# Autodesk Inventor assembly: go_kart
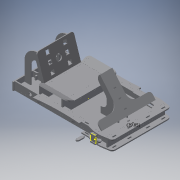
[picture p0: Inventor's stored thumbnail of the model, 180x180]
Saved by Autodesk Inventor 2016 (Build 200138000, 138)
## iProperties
Created: 2017-06
Part Number: go_kart
Document SubType Name: Assembly
Designer: laboratorioesan
Author: laboratorioesan
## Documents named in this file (25)
- C:\Users\laboratorioesan\Desktop\Proyecto final\go_kart.iam
- C:\Users\laboratorioesan\Desktop\Proyecto final\marco_lateral.ipt
- C:\Users\laboratorioesan\Desktop\Proyecto final\Part3.ipt
- C:\Users\laboratorioesan\Desktop\Proyecto final\marco_frontal.ipt
- C:\Users\laboratorioesan\Desktop\Proyecto final\base_marco.ipt
- C:\Users\laboratorioesan\Desktop\Proyecto final\transversal_marco.ipt
- C:\Users\laboratorioesan\Desktop\Proyecto final\asiento_base.ipt
- C:\Users\laboratorioesan\Desktop\Proyecto final\asiento_lateral.ipt
- C:\Users\laboratorioesan\Desktop\Proyecto final\fenders.ipt
- C:\Users\laboratorioesan\Desktop\Proyecto final\nervio_fender.ipt
- C:\Users\laboratorioesan\Desktop\Proyecto final\marco_frontal_1.ipt
- C:\Users\laboratorioesan\Desktop\Proyecto final\mascara_frontal.ipt
- C:\Users\laboratorioesan\Desktop\Proyecto final\uniones_mascara.ipt
- C:\Users\laboratorioesan\Desktop\Proyecto final\acople_nuevo.ipt
- C:\Users\laboratorioesan\Desktop\Proyecto final\acople_union_1.ipt
- C:\Users\laboratorioesan\Desktop\Proyecto final\acople_eje.ipt
- C:\Users\laboratorioesan\Desktop\Proyecto final\frontal_timon_estructura.ipt
- C:\Users\laboratorioesan\Desktop\Proyecto final\lateral_timon_estructura.ipt
- C:\Users\laboratorioesan\Desktop\Proyecto final\union_mascara.ipt
- C:\Users\laboratorioesan\Desktop\Proyecto final\espaldar_asiento.ipt
- C:\Users\laboratorioesan\Desktop\Proyecto final\espaldar_union_vertical.ipt
- C:\Users\laboratorioesan\Desktop\Proyecto final\chumaceras.ipt
- C:\Users\laboratorioesan\Desktop\Proyecto final\Soporte_eje_pequeño.ipt
- C:\Users\laboratorioesan\Desktop\Proyecto final\acople_union_2.ipt
- C:\Users\laboratorioesan\Desktop\Proyecto final\union_eje_pequeño.ipt
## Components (36 placed, 24 different names)
1. marco_lateral:1 — Flush:1, Mate:4, Mate:6, Mate:7, Flush:2, Flush:3, Mate:14, Mate:15, Mate:22, Mate:23, Mate:24, Mate:25, Mate:26, Mate:27, Mate:28
2. Part3:1 — Flush:1, Mate:1, Mate:2, Mate:3
3. marco_lateral:4 — Mate:1, Mate:2, Mate:3, Mate:5, Mate:8, Mate:9, Mate:13, Flush:6, Flush:7, Mate:19
4. marco_frontal:1 — Mate:4, Mate:5, Mate:6, Mate:7, Mate:8, Mate:9, Flush:20, Mate:50, Mate:51
5. base_marco:1 — Flush:2, Flush:8, Mate:40, Flush:18, Mate:46
6. transversal_marco:1 — Flush:3, Flush:5, Mate:17, Mate:18
7. transversal_marco:2 — Mate:13, Mate:14, Mate:15, Flush:4, Mate:16, Mate:29, Mate:30, Mate:49
8. asiento_base:1 — Flush:4, Flush:17
9. asiento_lateral:1 — Flush:5
10. asiento_lateral:2 — Mate:16, Mate:17, Mate:18
11. fenders:1 — Flush:6, Mate:20, Mate:21
12. nervio_fender:1 — Flush:7
13. nervio_fender:2 — Mate:19, Mate:20, Mate:21
14. nervio_fender:3 — Mate:22, Mate:23, Mate:24
15. nervio_fender:4 — Mate:25, Mate:26, Mate:27
16. fenders:2 — Mate:28, Mate:29, Mate:30
17. marco_frontal_1:1 — Flush:8, Flush:9, Mate:31, Mate:32, Mate:33
18. mascara_frontal:1 — Flush:9, Flush:12, Mate:43
19. mascara_frontal:2 — Mate:31, Mate:32, Mate:33, Flush:10, Flush:11, Mate:44, Mate:45
20. uniones_mascara:1 — Flush:10
21. acople_nuevo:1 — Flush:11, Flush:12, Mate:34, Mate:35, Mate:36
22. acople_union_1:1 — Mate:34, Mate:35, Mate:36, Mate:37, Mate:38, Mate:39
23. acople_nuevo:2 — Mate:37, Mate:38, Mate:39
24. acople_eje:1
25. frontal_timon_estructura:1 — Flush:16, Mate:41, Mate:42, Flush:19
26. lateral_timon_estructura:1 — Flush:16
27. lateral_timon_estructura:2 — Mate:40, Mate:41, Mate:42
28. union_mascara:1 — Mate:43, Mate:44, Mate:45
29. espaldar_asiento:1 — Flush:17, Mate:47, Mate:48
30. espaldar_union_vertical:1 — Flush:18
31. espaldar_union_vertical:2 — Mate:46, Mate:47, Mate:48
32. chumaceras:1 — Flush:19
33. Soporte_eje_pequeño:1 — Flush:20, Flush:21
34. Soporte_eje_pequeño:2 — Mate:49, Mate:50, Mate:51
35. acople_union_2:1
36. union_eje_pequeño:1 — Flush:21
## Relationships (66: Mate 48, Flush 18)
- Flush:1: marco_lateral:1 ↔ Part3:1
- Mate:1: Part3:1 ↔ marco_lateral:4
- Mate:2: Part3:1 ↔ marco_lateral:4
- Mate:3: Part3:1 ↔ marco_lateral:4
- Mate:4: marco_lateral:1 ↔ marco_frontal:1
- Mate:5: marco_lateral:4 ↔ marco_frontal:1
- Mate:6: marco_lateral:1 ↔ marco_frontal:1
- Mate:7: marco_lateral:1 ↔ marco_frontal:1
- Mate:8: marco_lateral:4 ↔ marco_frontal:1
- Mate:9: marco_lateral:4 ↔ marco_frontal:1
- Flush:2: marco_lateral:1 ↔ base_marco:1
- Flush:3: marco_lateral:1 ↔ transversal_marco:1
- Mate:13: marco_lateral:4 ↔ transversal_marco:2
- Mate:14: marco_lateral:1 ↔ transversal_marco:2
- Mate:15: marco_lateral:1 ↔ transversal_marco:2
- Flush:4: transversal_marco:2 ↔ asiento_base:1
- Flush:5: transversal_marco:1 ↔ asiento_lateral:1
- Mate:16: transversal_marco:2 ↔ asiento_lateral:2
- Mate:17: transversal_marco:1 ↔ asiento_lateral:2
- Mate:18: transversal_marco:1 ↔ asiento_lateral:2
- Flush:6: marco_lateral:4 ↔ fenders:1
- Flush:7: marco_lateral:4 ↔ nervio_fender:1
- Mate:19: marco_lateral:4 ↔ nervio_fender:2
- Mate:20: fenders:1 ↔ nervio_fender:2
- Mate:21: fenders:1 ↔ nervio_fender:2
- Mate:22: marco_lateral:1 ↔ nervio_fender:3
- Mate:23: marco_lateral:1 ↔ nervio_fender:3
- Mate:24: marco_lateral:1 ↔ nervio_fender:3
- Mate:25: marco_lateral:1 ↔ nervio_fender:4
- Mate:26: marco_lateral:1 ↔ nervio_fender:4
- Mate:27: marco_lateral:1 ↔ nervio_fender:4
- Mate:28: marco_lateral:1 ↔ fenders:2
- Mate:29: transversal_marco:2 ↔ fenders:2
- Mate:30: transversal_marco:2 ↔ fenders:2
- Flush:8: base_marco:1 ↔ marco_frontal_1:1
- Flush:9: marco_frontal_1:1 ↔ mascara_frontal:1
- Mate:31: marco_frontal_1:1 ↔ mascara_frontal:2
- Mate:32: marco_frontal_1:1 ↔ mascara_frontal:2
- Mate:33: marco_frontal_1:1 ↔ mascara_frontal:2
- Flush:10: mascara_frontal:2 ↔ uniones_mascara:1
- Flush:11: mascara_frontal:2 ↔ acople_nuevo:1
- Flush:12: mascara_frontal:1 ↔ acople_nuevo:1
- Mate:34: acople_nuevo:1 ↔ acople_union_1:1
- Mate:35: acople_nuevo:1 ↔ acople_union_1:1
- Mate:36: acople_nuevo:1 ↔ acople_union_1:1
- Mate:37: acople_union_1:1 ↔ acople_nuevo:2
- Mate:38: acople_union_1:1 ↔ acople_nuevo:2
- Mate:39: acople_union_1:1 ↔ acople_nuevo:2
- Flush:16: frontal_timon_estructura:1 ↔ lateral_timon_estructura:1
- Mate:40: base_marco:1 ↔ lateral_timon_estructura:2
- Mate:41: frontal_timon_estructura:1 ↔ lateral_timon_estructura:2
- Mate:42: frontal_timon_estructura:1 ↔ lateral_timon_estructura:2
- Mate:43: mascara_frontal:1 ↔ union_mascara:1
- Mate:44: mascara_frontal:2 ↔ union_mascara:1
- Mate:45: mascara_frontal:2 ↔ union_mascara:1
- Flush:17: asiento_base:1 ↔ espaldar_asiento:1
- Flush:18: base_marco:1 ↔ espaldar_union_vertical:1
- Mate:46: base_marco:1 ↔ espaldar_union_vertical:2
- Mate:47: espaldar_asiento:1 ↔ espaldar_union_vertical:2
- Mate:48: espaldar_asiento:1 ↔ espaldar_union_vertical:2
- Flush:19: frontal_timon_estructura:1 ↔ chumaceras:1
- Flush:20: marco_frontal:1 ↔ Soporte_eje_pequeño:1
- Mate:49: transversal_marco:2 ↔ Soporte_eje_pequeño:2
- Mate:50: marco_frontal:1 ↔ Soporte_eje_pequeño:2
- Mate:51: marco_frontal:1 ↔ Soporte_eje_pequeño:2
- Flush:21: Soporte_eje_pequeño:1 ↔ union_eje_pequeño:1
